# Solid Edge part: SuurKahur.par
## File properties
Author: Egon 815
Template: Normal.par
Last saved by: Egon 815
Revision: 6
Application: Solid Edge
Accuracy: 0,990
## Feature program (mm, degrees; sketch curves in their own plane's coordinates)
sketch for "unnamed Protrusion 1" plane through (0, 0, 6900) normal (0, 0, 1) x-axis (1, 0, 0)
  circle centre (0, -60705.8699) radius 5447.2462
extrude "unnamed Protrusion 1" add to key point along +normal
sketch for "unnamed Cutout 1" plane through (0, 0, 6900) normal (0, 0, 1) x-axis (1, 0, 0)
  circle centre (0, -60705.8699) radius 4953.3647
extrude "unnamed Cutout 1" cut through along +normal
chamfer "Chamfer_1" setback 100
sketch for "unnamed Protrusion 2" plane through (0, 0, 6900) normal (0, 0, 1) x-axis (1, 0, 0)
  circle centre (0, -60705.8699) radius 4953.3647
extrude "unnamed Protrusion 2" add to key point along +normal
lofted protrusion "unnamed LoftedProtrusion 1"
lofted protrusion "unnamed LoftedProtrusion 2"
mirror "unnamed Mirror 1" of "unnamed LoftedProtrusion 2", "unnamed LoftedProtrusion 1" about plane through (0, 0, 0) normal (1, 0, 0)
lofted protrusion "unnamed LoftedProtrusion 3"
lofted protrusion "unnamed LoftedProtrusion 4"
sketch for "ExtrudedCutout_2" plane through (0, 0, 8310) normal (0, 0, 1) x-axis (1, 0, 0)
  line (2325.4821, -64223.4789) -> (2325.4821, -66517.7636)
  line (820.8626, -64223.4789) -> (2325.4821, -64223.4789)
  line (820.8626, -66733.4908) -> (820.8626, -64223.4789)
extrude "ExtrudedCutout_2" cut finite 3945.4531 along +normal
mirror "unnamed Mirror 2" of "ExtrudedCutout_2" about plane through (0, 0, 0) normal (1, 0, 0)
extrude "unnamed Cutout 2" cut finite 3945.4531
lofted protrusion "unnamed LoftedProtrusion 5"
sketch for "unnamed Cutout 3" plane through (1573.1723, -77940.3377, 9291.1954) normal (0, -1, 0) x-axis (1, 0, 0)
  circle centre (-2.3344, -81.4772) radius 300
extrude "unnamed Cutout 3" cut finite 19682.3795 along -normal
mirror "unnamed Mirror 3" of "unnamed Cutout 3", "unnamed LoftedProtrusion 5" about plane through (0, 0, 0) normal (1, 0, 0)
lofted protrusion "unnamed LoftedProtrusion 6"
extrude "unnamed Cutout 4" cut finite 19682.3795
chamfer "unnamed Chamfer 1"
chamfer "Chamfer_6" setback 100
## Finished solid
Body 1: solid body, 103 faces, 263 edges, 164 vertices, 2 separate solids.
  Faces by surface: spline 55, plane 40, cone 4, cylinder 4
  Edges by curve: curve on surface 103, line 101, spline 22, intersection 20, circle 17
Bounding box of the edges (mm; curved faces can reach further): 12032.655 x 24114.617 x 4579.732, from (-6016.3272, -77940.3377, 6900) to (6016.3272, -53825.7211, 11479.7317).
Cylindrical faces by radius (mm): R300 x2, R4953.3647 x1, R5447.2462 x1
Conical faces (half-angle, radius in mm at the cone's reference point): 1.2813 deg R706.7909 x2, 45 deg R5053.3647 x1, 45 deg R5447.2462 x1
Planar faces by outward normal: +x 5, +z 4, -x 5, -y 8, -z 2, oblique 16
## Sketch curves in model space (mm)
circle centre (1570.8379, -77940.3377, 9209.7182) radius 300
circle centre (1570.8379, -77940.3377, 9209.7182) radius 400
circle centre (1570.8379, -64223.4789, 9209.7182) radius 706.7909
line (4746.6775, -64585.2769, 8937.7826) -> (4746.6775, -62897.3667, 10200.3285)
line (4746.6775, -62897.3667, 10200.3285) -> (4746.6775, -55827.7733, 10676.1317)
line (4746.6775, -55827.7733, 10676.1317) -> (4746.6775, -54663.6583, 10676.1317)
line (4746.6775, -54663.6583, 10676.1317) -> (4746.6775, -54663.6583, 8395.553)
line (4746.6775, -54663.6583, 8395.553) -> (4746.6775, -64585.2769, 8395.553)
line (4746.6775, -64585.2769, 8395.553) -> (4746.6775, -64585.2769, 8937.7826)
line (6016.3272, -58679.2732, 8781.1583) -> (6016.3272, -58679.2732, 9460.0306)
line (6016.3272, -58679.2732, 9460.0306) -> (6016.3272, -61986.1726, 9460.0306)
line (6016.3272, -61986.1726, 9460.0306) -> (6016.3272, -61986.1726, 8781.1583)
line (6016.3272, -61986.1726, 8781.1583) -> (6016.3272, -58679.2732, 8781.1583)
line (0, -53825.7211, 11479.7317) -> (0, -55827.7733, 11479.7317)
line (0, -55827.7733, 11479.7317) -> (0, -63097.9632, 10676.1317)
line (0, -63097.9632, 10676.1317) -> (0, -64522.3166, 10200.3285)
line (0, -64522.3166, 10200.3285) -> (0, -66306.4153, 8937.7826)
line (0, -66306.4153, 8937.7826) -> (0, -66757.0108, 8395.553)
line (0, -66757.0108, 8395.553) -> (0, -53825.7211, 8395.553)
line (0, -53825.7211, 8395.553) -> (0, -53825.7211, 11479.7317)
line (6016.3272, -62130.6591, 6900) -> (3799.5601, -66306.4153, 6900)
line (6016.3272, -62130.6591, 6900) -> (6016.3272, -58753.6512, 6900)
line (6016.3272, -58753.6512, 6900) -> (4394.2112, -54476.1078, 6900)
line (4394.2112, -54476.1078, 6900) -> (0, -53825.7211, 6900)
line (0, -53825.7211, 6900) -> (0, -66851.1833, 6900)
line (0, -66851.1833, 6900) -> (3799.5601, -66306.4153, 6900)
line (6016.3272, -60705.8699, 8937.7826) -> (4746.6775, -60705.8699, 10200.3285)
line (4746.6775, -60705.8699, 10200.3285) -> (2817.3601, -60705.8699, 11107.0601)
line (2817.3601, -60705.8699, 11107.0601) -> (0, -60705.8699, 11479.7317)
line (-2817.3601, -60705.8699, 11107.0601) -> (0, -60705.8699, 11479.7317)
line (-4746.6775, -60705.8699, 10200.3285) -> (-2817.3601, -60705.8699, 11107.0601)
line (-6016.3272, -60705.8699, 8937.7826) -> (-4746.6775, -60705.8699, 10200.3285)
line (-6016.3272, -60705.8699, 8395.553) -> (-6016.3272, -60705.8699, 8937.7826)
line (-6016.3272, -60705.8699, 8395.553) -> (6016.3272, -60705.8699, 8395.553)
line (6016.3272, -60705.8699, 8395.553) -> (6016.3272, -60705.8699, 8937.7826)
circle centre (0, -60705.8699, 6900) radius 4953.3647
circle centre (0, -60705.8699, 6900) radius 5447.2462
line (0, -53392.2096, 6900) -> (0, -66851.1833, 6900)
circle centre (1553.0628, 0, 8932.106) radius 675.2464
circle centre (1553.0628, 0, 8932.106) radius 353.597
circle centre (1553.0628, 0, 8932.106) radius 210.8001
line (3614.1063, 0, 8472.6575) -> (3614.1063, 0, 10104.702)
line (3614.1063, 0, 10104.702) -> (0, 0, 10336.0154)
line (0, 0, 10336.0154) -> (-3620.8628, 0, 10104.702)
line (-3620.8628, 0, 10104.702) -> (-3620.8628, 0, 8472.6575)
line (-3620.8628, 0, 8472.6575) -> (3614.1063, 0, 8472.6575)
line (2817.3601, 0, 11107.0601) -> (0, 0, 11479.7317)
line (4025.3301, 0, 10104.702) -> (2817.3601, 0, 11107.0601)
line (4744.9718, 0, 9320.8066) -> (4025.3301, 0, 10104.702)
line (4744.9718, 0, 8395.553) -> (4744.9718, 0, 9320.8066)
line (4744.9718, 0, 8395.553) -> (0, 0, 8395.553)
line (2277.6289, 0, 10079.0005) -> (2277.6289, 0, 8472.6575)
line (864.047, 0, 10168.9557) -> (2277.6289, 0, 10079.0005)
line (864.047, 0, 8472.6575) -> (864.047, 0, 10168.9557)
line (0, -54662.205, 8314.9532) -> (0, -54662.205, 6344.2559)
line (0, -66107.4769, 8314.9532) -> (0, -66107.4769, 6344.2559)
line (0, -66882.6547, 9878.1546) -> (0, -64602.72, 9878.1546)
line (0, -66882.6547, 9148.5755) -> (0, -66882.6547, 9878.1546)
line (0, -77940.3377, 9148.5755) -> (0, -66882.6547, 9148.5755)
line (0, -77940.3377, 8464.5951) -> (0, -66403.8684, 8314.9532)
line (0, -77940.3377, 8464.5951) -> (0, -77940.3377, 9148.5755)
line (0, -53567.8364, 8314.9532) -> (0, -66403.8684, 8314.9532)
line (0, -53567.8364, 11451.3095) -> (0, -53567.8364, 8314.9532)
line (0, -63097.9632, 10676.1317) -> (0, -53567.8364, 11451.3095)
line (0, -64602.72, 9878.1546) -> (0, -63097.9632, 10676.1317)
line (0, -66403.8684, 8601.3912) -> (0, -64602.72, 9878.1546)
line (0, -66403.8684, 8314.9532) -> (0, -66403.8684, 8601.3912)
line (0, -66403.8684, 7757.8154) -> (0, -66403.8684, 6344.2559)
line (0, -54229.0174, 7757.8154) -> (0, -54229.0174, 5842.6703)
line (0, -54229.0174, 7757.8154) -> (0, -66403.8684, 7757.8154)
line (3799.5601, -66306.4153, 8310) -> (6074.7676, -62204.6328, 8310)
line (3799.5601, -66306.4153, 8310) -> (3799.5601, -63838.9368, 8310)
line (3799.5601, -63838.9368, 8310) -> (6074.7676, -62204.6328, 8310)
line (3799.5601, -63838.9368, 8310) -> (0, -63838.9368, 8310)
line (6074.7676, -62204.6328, 8310) -> (6074.7676, -58743.7539, 8310)
line (6074.7676, -58743.7539, 8310) -> (4857.0509, -56116.0495, 8310)
line (4857.0509, -56116.0495, 8310) -> (3799.5601, -53744.7065, 8310)
line (3799.5601, -53744.7065, 8310) -> (0, -53392.2096, 8310)
line (-3799.5601, -53744.7065, 8310) -> (0, -53392.2096, 8310)
line (-4857.0509, -56116.0495, 8310) -> (-3799.5601, -53744.7065, 8310)
line (-6074.7676, -58743.7539, 8310) -> (-4857.0509, -56116.0495, 8310)
line (-6074.7676, -62204.6328, 8310) -> (-6074.7676, -58743.7539, 8310)
line (-3799.5601, -66306.4153, 8310) -> (-6074.7676, -62204.6328, 8310)
line (0, -66851.1833, 8310) -> (-3799.5601, -66306.4153, 8310)
line (0, -66851.1833, 8310) -> (3799.5601, -66306.4153, 8310)
line (2325.4821, -64223.4789, 8310) -> (2325.4821, -66517.7636, 8310)
line (820.8626, -64223.4789, 8310) -> (2325.4821, -64223.4789, 8310)
line (820.8626, -66733.4908, 8310) -> (820.8626, -64223.4789, 8310)
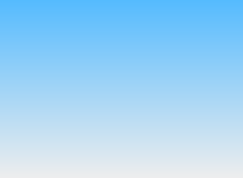
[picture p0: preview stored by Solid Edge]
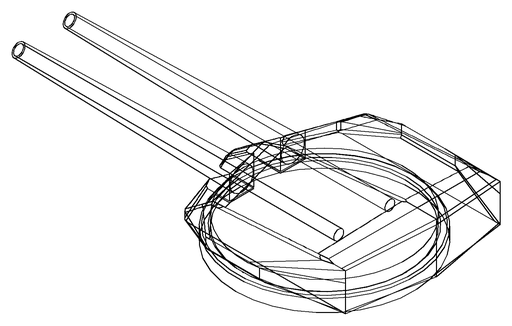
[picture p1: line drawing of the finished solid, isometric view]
